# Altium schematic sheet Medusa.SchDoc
size A3; SheetNumber: 1; SheetTotal: 3
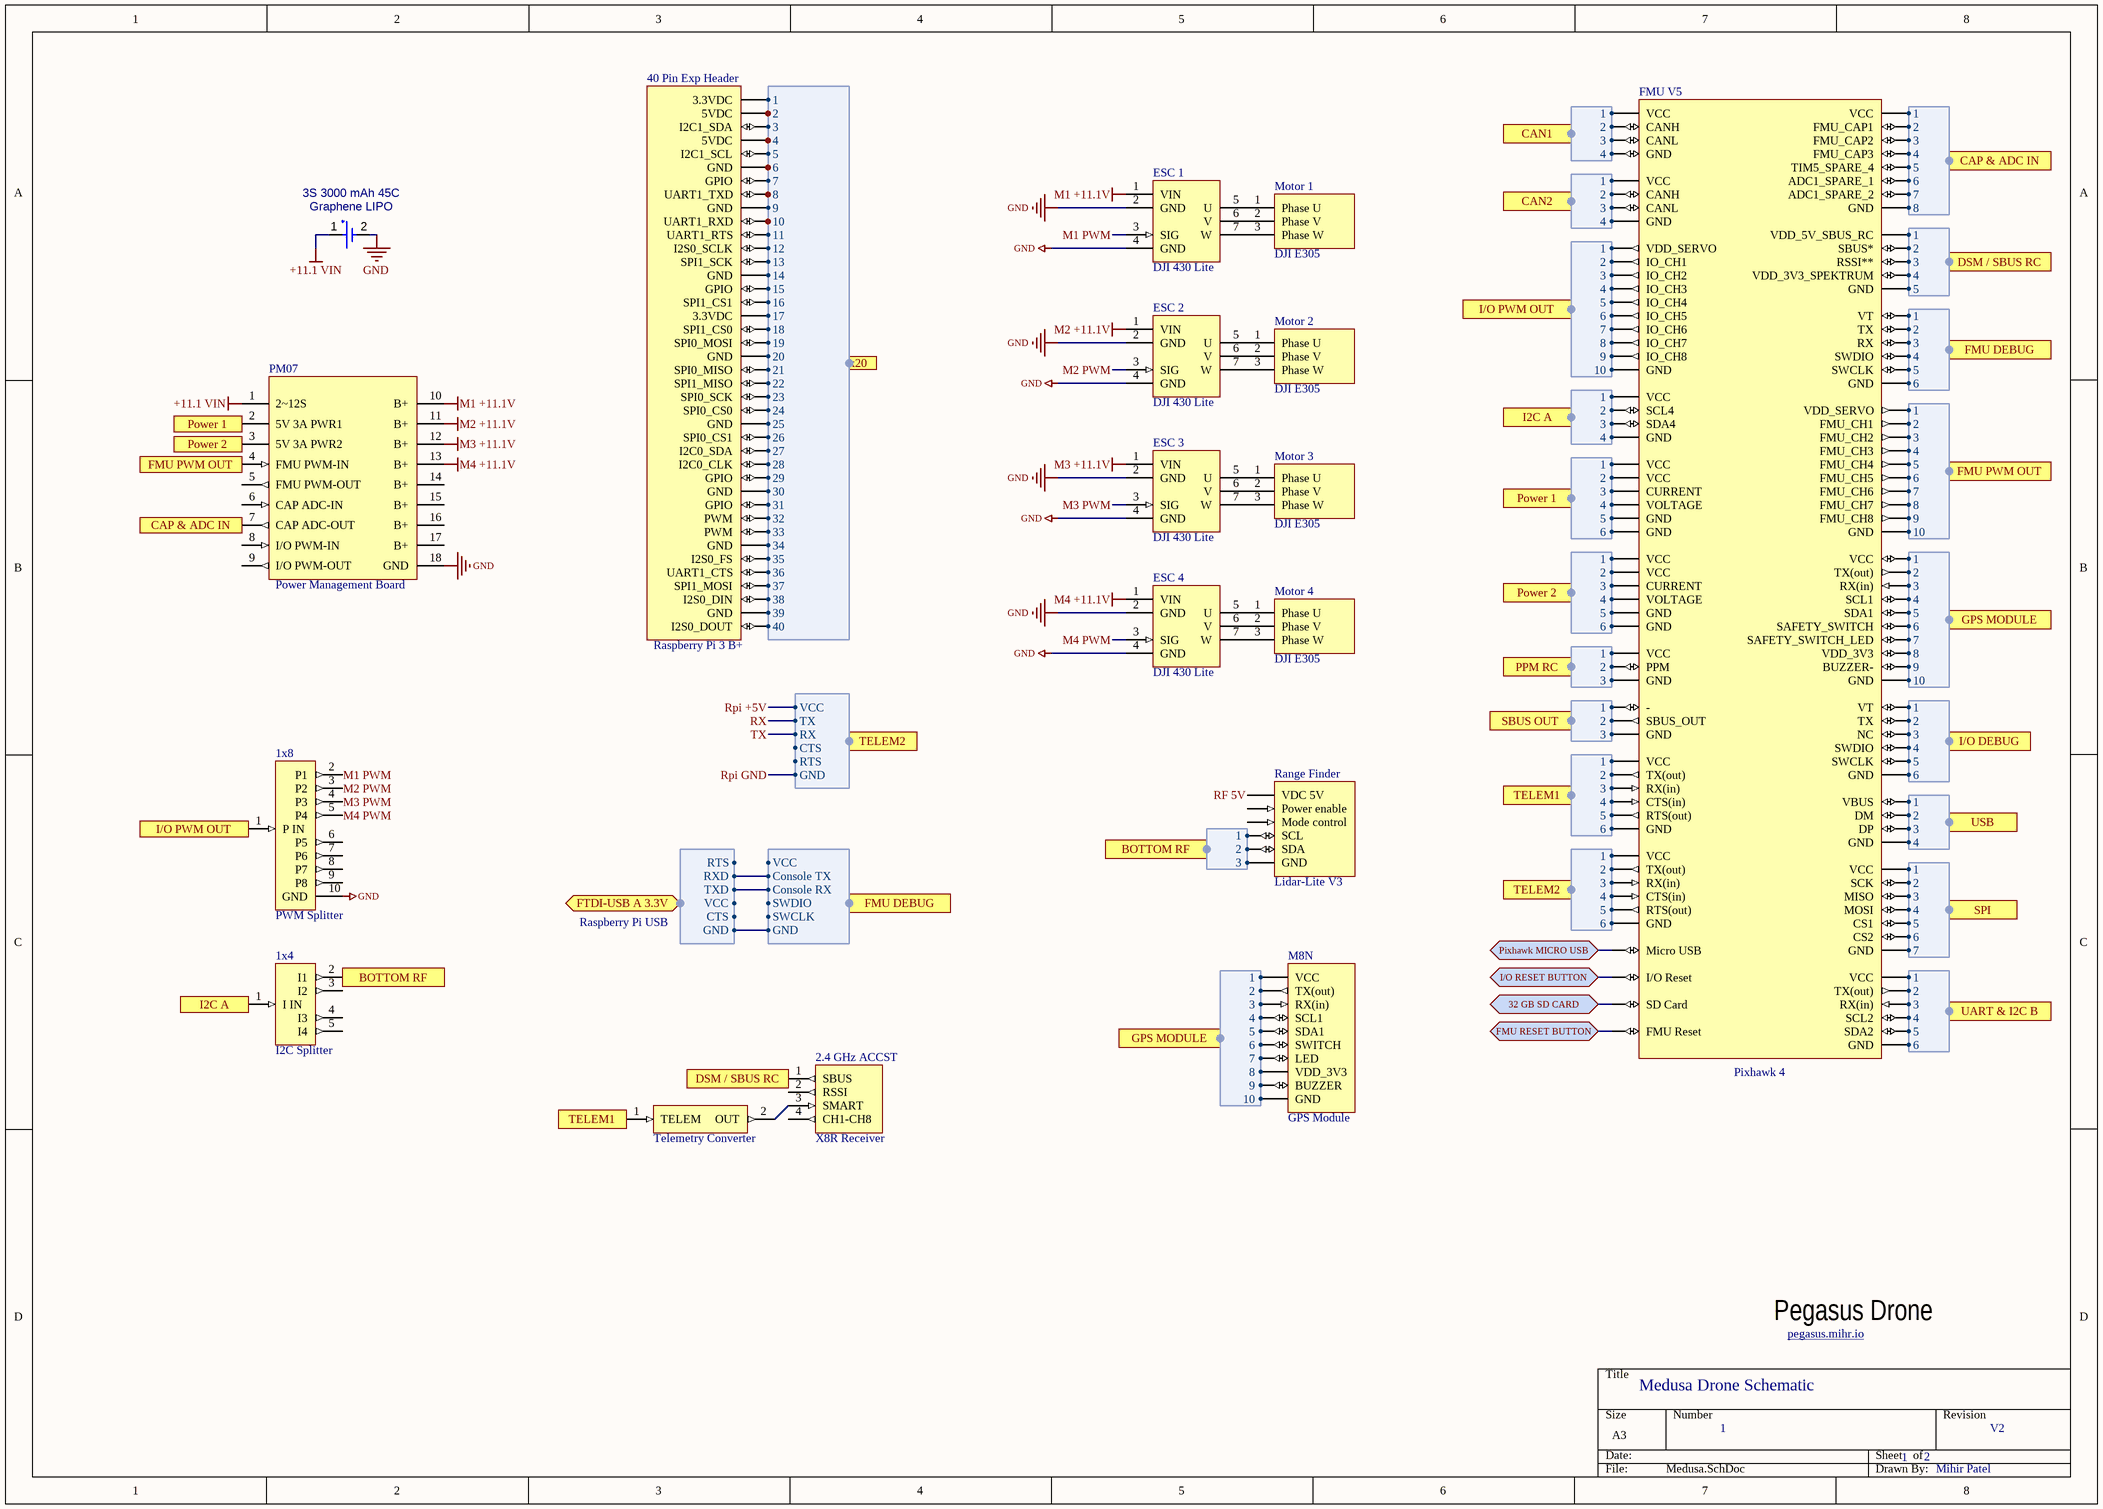
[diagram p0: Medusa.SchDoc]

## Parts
1x4  I2C Splitter
1x8  PWM Splitter
2.4_GHz_ACCST  X8R Receiver
3S_3000_mAh_45C  Graphene LIPO  [SEIK-MS621FE-FL11E-2_V]
40_Pin_Exp_Header  Raspberry Pi 3 B+
ESC_1  DJI 430 Lite
ESC_2  DJI 430 Lite
ESC_3  DJI 430 Lite
ESC_4  DJI 430 Lite
FMU_V5  Pixhawk 4
M8N  GPS Module
Motor_1  DJI E305
Motor_2  DJI E305
Motor_3  DJI E305
Motor_4  DJI E305
PM07  Power Management Board
Range_Finder  Lidar-Lite V3
TC?  Telemetry Converter

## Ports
2x20 (harness NX), 32 GB SD CARD (bidir), BOTTOM RF (harness *), BOTTOM RF (harness xx), CAN1 (harness CAN1), CAN2 (harness CAN2), CAP & ADC IN (harness CAP & ADC IN), DSM / SBUS RC (harness DSM / SBUS RC), FMU DEBUG (harness FDD), FMU DEBUG (harness FMU DEBUG), FMU PWM OUT (harness FMU PWM OUT), FMU RESET BUTTON (bidir), FTDI-USB A 3.3V (bidir, harness USBD), GPS MODULE (harness GPS MODULE), GPS MODULE (harness GPS), I2C A (harness I2C A), I/O DEBUG (harness IO DEBUG), I/O PWM OUT (harness I/O PWM OUT), I/O RESET BUTTON (bidir), Pixhawk MICRO USB (bidir), Power 1 (harness Power 1), Power 2 (harness Power 2), PPM RC (harness PPM RC), SBUS OUT (harness SBUS OUT), SPI (harness SPI), TELEM1 (harness TELEM1), TELEM2 (harness TELEM2), TELEM2 (harness X1), UART & I2C B (harness UART & I2C B), USB (harness USB)

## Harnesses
CAP & ADC IN: 1, 2, 3, 4, 5, 6, 7, 8
DSM / SBUS RC: 1, 2, 3, 4, 5
FMU DEBUG: 1, 2, 3, 4, 5, 6
FMU PWM OUT: 1, 2, 3, 4, 5, 6, 7, 8, 9, 10
IO DEBUG: 1, 2, 3, 4, 5, 6
SPI: 1, 2, 3, 4, 5, 6, 7
CAN1: 1, 2, 3, 4
CAN2: 1, 2, 3, 4
I/O PWM OUT: 1, 2, 3, 4, 5, 6, 7, 8, 9, 10
I2C A: 1, 2, 3, 4
Power 1: 1, 2, 3, 4, 5, 6
Power 2: 1, 2, 3, 4, 5, 6
SBUS OUT: 1, 2, 3
TELEM1: 1, 2, 3, 4, 5, 6
TELEM2: 1, 2, 3, 4, 5, 6
GPS MODULE: 1, 2, 3, 4, 5, 6, 7, 8, 9, 10
PPM RC: 1, 2, 3
USB: 1, 2, 3, 4
UART & I2C B: 1, 2, 3, 4, 5, 6
GPS: 1, 2, 3, 4, 5, 6, 7, 8, 9, 10
NX: 1, 2, 3, 4, 5, 6, 7, 8, 9, 10, 11, 12, 13, 14, 15, 16, 17, 18, 19, 20, 21, 22, 23, 24, 25, 26, 27, 28, 29, 30, 31, 32, 33, 34, 35, 36, 37, 38, 39, 40
FDD: VCC, Console TX, Console RX, SWDIO, SWCLK, GND
USBD: GND, CTS, VCC, TXD, RXD, RTS
xx: 1, 2, 3
X1: VCC, TX, RX, CTS, RTS, GND

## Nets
+11.1 VIN: 3S_3000_mAh_45C.1(+) PM07.1(2~12S)
GND: 1x8.10(GND) 3S_3000_mAh_45C.2(-) ESC_1.2(GND) ESC_1.4(GND) ESC_2.2(GND) ESC_2.4(GND) ESC_3.2(GND) ESC_3.4(GND) ESC_4.2(GND) ESC_4.4(GND) PM07.18(GND)
M1 +11.1V: ESC_1.1(VIN) PM07.10(B+)
M2 +11.1V: ESC_2.1(VIN) PM07.11(B+)
M3 +11.1V: ESC_3.1(VIN) PM07.12(B+)
M4 +11.1V: ESC_4.1(VIN) PM07.13(B+)
32 GB SD CARD: FMU_V5.117(SD_Card) ; port 32 GB SD CARD
FMU RESET BUTTON: FMU_V5.118(FMU_Reset) ; port FMU RESET BUTTON
I/O RESET BUTTON: FMU_V5.116(I/O_Reset) ; port I/O RESET BUTTON
M1 PWM: 1x8.2(P1) ESC_1.3(SIG)
M2 PWM: 1x8.3(P2) ESC_2.3(SIG)
M3 PWM: 1x8.4(P3) ESC_3.3(SIG)
M4 PWM: 1x8.5(P4) ESC_4.3(SIG)
Pixhawk MICRO USB: FMU_V5.115(Micro_USB) ; port Pixhawk MICRO USB
RF 5V: 40_Pin_Exp_Header.2(5VDC) Range_Finder.1(VDC_5V) ; harness NX.2
Rpi +5V: 40_Pin_Exp_Header.4(5VDC) ; harness NX.4, port TELEM2.VCC
Rpi GND: 40_Pin_Exp_Header.6(GND) ; harness NX.6, port TELEM2.GND
RX: 40_Pin_Exp_Header.10(UART1_RXD) ; harness NX.10, port TELEM2.TX
TX: 40_Pin_Exp_Header.8(UART1_TXD) ; harness NX.8, port TELEM2.RX
Net2.4_GHz_ACCST_3: 2.4_GHz_ACCST.3(SMART) TC?.2(OUT)
Net40_Pin_Exp_Header_1: 40_Pin_Exp_Header.1(3.3VDC) ; harness NX.1
Net40_Pin_Exp_Header_3: 40_Pin_Exp_Header.3(I2C1_SDA) ; harness NX.3
Net40_Pin_Exp_Header_5: 40_Pin_Exp_Header.5(I2C1_SCL) ; harness NX.5
Net40_Pin_Exp_Header_7: 40_Pin_Exp_Header.7(GPIO) ; harness NX.7
Net40_Pin_Exp_Header_9: 40_Pin_Exp_Header.9(GND) ; harness NX.9
Net40_Pin_Exp_Header_11: 40_Pin_Exp_Header.11(UART1_RTS) ; harness NX.11
Net40_Pin_Exp_Header_12: 40_Pin_Exp_Header.12(I2S0_SCLK) ; harness NX.12
Net40_Pin_Exp_Header_13: 40_Pin_Exp_Header.13(SPI1_SCK) ; harness NX.13
Net40_Pin_Exp_Header_14: 40_Pin_Exp_Header.14(GND) ; harness NX.14
Net40_Pin_Exp_Header_15: 40_Pin_Exp_Header.15(GPIO) ; harness NX.15
Net40_Pin_Exp_Header_16: 40_Pin_Exp_Header.16(SPI1_CS1) ; harness NX.16
Net40_Pin_Exp_Header_17: 40_Pin_Exp_Header.17(3.3VDC) ; harness NX.17
Net40_Pin_Exp_Header_18: 40_Pin_Exp_Header.18(SPI1_CS0) ; harness NX.18
Net40_Pin_Exp_Header_19: 40_Pin_Exp_Header.19(SPI0_MOSI) ; harness NX.19
Net40_Pin_Exp_Header_20: 40_Pin_Exp_Header.20(GND) ; harness NX.20
Net40_Pin_Exp_Header_21: 40_Pin_Exp_Header.21(SPI0_MISO) ; harness NX.21
Net40_Pin_Exp_Header_22: 40_Pin_Exp_Header.22(SPI1_MISO) ; harness NX.22
Net40_Pin_Exp_Header_23: 40_Pin_Exp_Header.23(SPI0_SCK) ; harness NX.23
Net40_Pin_Exp_Header_24: 40_Pin_Exp_Header.24(SPI0_CS0) ; harness NX.24
Net40_Pin_Exp_Header_25: 40_Pin_Exp_Header.25(GND) ; harness NX.25
Net40_Pin_Exp_Header_26: 40_Pin_Exp_Header.26(SPI0_CS1) ; harness NX.26
Net40_Pin_Exp_Header_27: 40_Pin_Exp_Header.27(I2C0_SDA) ; harness NX.27
Net40_Pin_Exp_Header_28: 40_Pin_Exp_Header.28(I2C0_CLK) ; harness NX.28
Net40_Pin_Exp_Header_29: 40_Pin_Exp_Header.29(GPIO) ; harness NX.29
Net40_Pin_Exp_Header_30: 40_Pin_Exp_Header.30(GND) ; harness NX.30
Net40_Pin_Exp_Header_31: 40_Pin_Exp_Header.31(GPIO) ; harness NX.31
Net40_Pin_Exp_Header_32: 40_Pin_Exp_Header.32(PWM) ; harness NX.32
Net40_Pin_Exp_Header_33: 40_Pin_Exp_Header.33(PWM) ; harness NX.33
Net40_Pin_Exp_Header_34: 40_Pin_Exp_Header.34(GND) ; harness NX.34
Net40_Pin_Exp_Header_35: 40_Pin_Exp_Header.35(I2S0_FS) ; harness NX.35
Net40_Pin_Exp_Header_36: 40_Pin_Exp_Header.36(UART1_CTS) ; harness NX.36
Net40_Pin_Exp_Header_37: 40_Pin_Exp_Header.37(SPI1_MOSI) ; harness NX.37
Net40_Pin_Exp_Header_38: 40_Pin_Exp_Header.38(I2S0_DIN) ; harness NX.38
Net40_Pin_Exp_Header_39: 40_Pin_Exp_Header.39(GND) ; harness NX.39
Net40_Pin_Exp_Header_40: 40_Pin_Exp_Header.40(I2S0_DOUT) ; harness NX.40
NetESC_1_5: ESC_1.5(U) Motor_1.1(Phase_U)
NetESC_1_6: ESC_1.6(V) Motor_1.2(Phase_V)
NetESC_1_7: ESC_1.7(W) Motor_1.3(Phase_W)
NetESC_2_5: ESC_2.5(U) Motor_2.1(Phase_U)
NetESC_2_6: ESC_2.6(V) Motor_2.2(Phase_V)
NetESC_2_7: ESC_2.7(W) Motor_2.3(Phase_W)
NetESC_3_5: ESC_3.5(U) Motor_3.1(Phase_U)
NetESC_3_6: ESC_3.6(V) Motor_3.2(Phase_V)
NetESC_3_7: ESC_3.7(W) Motor_3.3(Phase_W)
NetESC_4_5: ESC_4.5(U) Motor_4.1(Phase_U)
NetESC_4_6: ESC_4.6(V) Motor_4.2(Phase_V)
NetESC_4_7: ESC_4.7(W) Motor_4.3(Phase_W)
NetFMU_V5_1: FMU_V5.1(VCC) ; port Power 1.1
NetFMU_V5_2: FMU_V5.2(VCC) ; port Power 1.2
NetFMU_V5_3: FMU_V5.3(CURRENT) ; port Power 1.3
NetFMU_V5_4: FMU_V5.4(VOLTAGE) ; port Power 1.4
NetFMU_V5_5: FMU_V5.5(GND) ; port Power 1.5
NetFMU_V5_6: FMU_V5.6(GND) ; port Power 1.6
NetFMU_V5_7: FMU_V5.7(VCC) ; port Power 2.1
NetFMU_V5_8: FMU_V5.8(VCC) ; port Power 2.2
NetFMU_V5_9: FMU_V5.9(CURRENT) ; port Power 2.3
NetFMU_V5_10: FMU_V5.10(VOLTAGE) ; port Power 2.4
NetFMU_V5_11: FMU_V5.11(GND) ; port Power 2.5
NetFMU_V5_12: FMU_V5.12(GND) ; port Power 2.6
NetFMU_V5_13: FMU_V5.13(VCC) ; port TELEM1.1
NetFMU_V5_14: FMU_V5.14(TX(out)) ; port TELEM1.2
NetFMU_V5_15: FMU_V5.15(RX(in)) ; port TELEM1.3
NetFMU_V5_16: FMU_V5.16(CTS(in)) ; port TELEM1.4
NetFMU_V5_17: FMU_V5.17(RTS(out)) ; port TELEM1.5
NetFMU_V5_18: FMU_V5.18(GND) ; port TELEM1.6
NetFMU_V5_19: FMU_V5.19(VBUS) ; port USB.1
NetFMU_V5_20: FMU_V5.20(DM) ; port USB.2
NetFMU_V5_21: FMU_V5.21(DP) ; port USB.3
NetFMU_V5_22: FMU_V5.22(GND) ; port USB.4
NetFMU_V5_23: FMU_V5.23(VCC) ; port TELEM2.1
NetFMU_V5_24: FMU_V5.24(TX(out)) ; port TELEM2.2
NetFMU_V5_25: FMU_V5.25(RX(in)) ; port TELEM2.3
NetFMU_V5_26: FMU_V5.26(CTS(in)) ; port TELEM2.4
NetFMU_V5_27: FMU_V5.27(RTS(out)) ; port TELEM2.5
NetFMU_V5_28: FMU_V5.28(GND) ; port TELEM2.6
NetFMU_V5_29: FMU_V5.29(VCC) ; port CAN1.1
NetFMU_V5_30: FMU_V5.30(CANH) ; port CAN1.2
NetFMU_V5_31: FMU_V5.31(CANL) ; port CAN1.3
NetFMU_V5_32: FMU_V5.32(GND) ; port CAN1.4
NetFMU_V5_33: FMU_V5.33(VCC) ; port I2C A.1
NetFMU_V5_34: FMU_V5.34(SCL4) ; port I2C A.2
NetFMU_V5_35: FMU_V5.35(SDA4) ; port I2C A.3
NetFMU_V5_36: FMU_V5.36(GND) ; port I2C A.4
NetFMU_V5_37: FMU_V5.37(VCC) ; port CAN2.1
NetFMU_V5_38: FMU_V5.38(CANH) ; port CAN2.2
NetFMU_V5_39: FMU_V5.39(CANL) ; port CAN2.3
NetFMU_V5_40: FMU_V5.40(GND) ; port CAN2.4
NetFMU_V5_41: FMU_V5.41(-) ; port SBUS OUT.1
NetFMU_V5_42: FMU_V5.42(SBUS_OUT) ; port SBUS OUT.2
NetFMU_V5_43: FMU_V5.43(GND) ; port SBUS OUT.3
NetFMU_V5_44: FMU_V5.44(VCC) ; port PPM RC.1
NetFMU_V5_45: FMU_V5.45(PPM) ; port PPM RC.2
NetFMU_V5_46: FMU_V5.46(GND) ; port PPM RC.3
NetFMU_V5_47: FMU_V5.47(VDD_SERVO) ; port I/O PWM OUT.1
NetFMU_V5_48: FMU_V5.48(IO_CH1) ; port I/O PWM OUT.2
NetFMU_V5_49: FMU_V5.49(IO_CH2) ; port I/O PWM OUT.3
NetFMU_V5_50: FMU_V5.50(IO_CH3) ; port I/O PWM OUT.4
NetFMU_V5_51: FMU_V5.51(IO_CH4) ; port I/O PWM OUT.5
NetFMU_V5_52: FMU_V5.52(IO_CH5) ; port I/O PWM OUT.6
NetFMU_V5_53: FMU_V5.53(IO_CH6) ; port I/O PWM OUT.7
NetFMU_V5_54: FMU_V5.54(IO_CH7) ; port I/O PWM OUT.8
NetFMU_V5_55: FMU_V5.55(IO_CH8) ; port I/O PWM OUT.9
NetFMU_V5_56: FMU_V5.56(GND) ; port I/O PWM OUT.10
NetFMU_V5_57: FMU_V5.57(VCC) ; port UART & I2C B.1
NetFMU_V5_58: FMU_V5.58(TX(out)) ; port UART & I2C B.2
NetFMU_V5_59: FMU_V5.59(RX(in)) ; port UART & I2C B.3
NetFMU_V5_60: FMU_V5.60(SCL2) ; port UART & I2C B.4
NetFMU_V5_61: FMU_V5.61(SDA2) ; port UART & I2C B.5
NetFMU_V5_62: FMU_V5.62(GND) ; port UART & I2C B.6
NetFMU_V5_63: FMU_V5.63(VDD_5V_SBUS_RC) ; port DSM / SBUS RC.1
NetFMU_V5_64: FMU_V5.64(SBUS*) ; port DSM / SBUS RC.2
NetFMU_V5_65: FMU_V5.65(RSSI**) ; port DSM / SBUS RC.3
NetFMU_V5_66: FMU_V5.66(VDD_3V3_SPEKTRUM) ; port DSM / SBUS RC.4
NetFMU_V5_67: FMU_V5.67(GND) ; port DSM / SBUS RC.5
NetFMU_V5_68: FMU_V5.68(VCC) ; port CAP & ADC IN.1
NetFMU_V5_69: FMU_V5.69(FMU_CAP1) ; port CAP & ADC IN.2
NetFMU_V5_70: FMU_V5.70(FMU_CAP2) ; port CAP & ADC IN.3
NetFMU_V5_71: FMU_V5.71(FMU_CAP3) ; port CAP & ADC IN.4
NetFMU_V5_72: FMU_V5.72(TIM5_SPARE_4) ; port CAP & ADC IN.5
NetFMU_V5_73: FMU_V5.73(ADC1_SPARE_1) ; port CAP & ADC IN.6
NetFMU_V5_74: FMU_V5.74(ADC1_SPARE_2) ; port CAP & ADC IN.7
NetFMU_V5_75: FMU_V5.75(GND) ; port CAP & ADC IN.8
NetFMU_V5_76: FMU_V5.76(VCC) M8N.1(VCC) ; port GPS MODULE.1
NetFMU_V5_77: FMU_V5.77(TX(out)) M8N.2(TX(out)) ; port GPS MODULE.2
NetFMU_V5_78: FMU_V5.78(RX(in)) M8N.3(RX(in)) ; port GPS MODULE.3
NetFMU_V5_79: FMU_V5.79(SCL1) M8N.4(SCL1) ; port GPS MODULE.4
NetFMU_V5_80: FMU_V5.80(SDA1) M8N.5(SDA1) ; port GPS MODULE.5
NetFMU_V5_81: FMU_V5.81(SAFETY_SWITCH) M8N.6(SWITCH) ; port GPS MODULE.6
NetFMU_V5_82: FMU_V5.82(SAFETY_SWITCH_LED) M8N.7(LED) ; port GPS MODULE.7
NetFMU_V5_83: FMU_V5.83(VDD_3V3) M8N.8(VDD_3V3) ; port GPS MODULE.8
NetFMU_V5_84: FMU_V5.84(BUZZER-) M8N.9(BUZZER) ; port GPS MODULE.9
NetFMU_V5_85: FMU_V5.85(GND) M8N.10(GND) ; port GPS MODULE.10
NetFMU_V5_86: FMU_V5.86(VCC) ; port SPI.1
NetFMU_V5_87: FMU_V5.87(SCK) ; port SPI.2
NetFMU_V5_88: FMU_V5.88(MISO) ; port SPI.3
NetFMU_V5_89: FMU_V5.89(MOSI) ; port SPI.4
NetFMU_V5_90: FMU_V5.90(CS1) ; port SPI.5
NetFMU_V5_91: FMU_V5.91(CS2) ; port SPI.6
NetFMU_V5_92: FMU_V5.92(GND) ; port SPI.7
NetFMU_V5_93: FMU_V5.93(VDD_SERVO) ; port FMU PWM OUT.1
NetFMU_V5_94: FMU_V5.94(FMU_CH1) ; port FMU PWM OUT.2
NetFMU_V5_95: FMU_V5.95(FMU_CH2) ; port FMU PWM OUT.3
NetFMU_V5_96: FMU_V5.96(FMU_CH3) ; port FMU PWM OUT.4
NetFMU_V5_97: FMU_V5.97(FMU_CH4) ; port FMU PWM OUT.5
NetFMU_V5_98: FMU_V5.98(FMU_CH5) ; port FMU PWM OUT.6
NetFMU_V5_99: FMU_V5.99(FMU_CH6) ; port FMU PWM OUT.7
NetFMU_V5_100: FMU_V5.100(FMU_CH7) ; port FMU PWM OUT.8
NetFMU_V5_101: FMU_V5.101(FMU_CH8) ; port FMU PWM OUT.9
NetFMU_V5_102: FMU_V5.102(GND) ; port FMU PWM OUT.10
NetFMU_V5_103: FMU_V5.103(VT) ; port FMU DEBUG.1
NetFMU_V5_104: FMU_V5.104(TX) ; port FMU DEBUG.2
NetFMU_V5_105: FMU_V5.105(RX) ; port FMU DEBUG.3
NetFMU_V5_106: FMU_V5.106(SWDIO) ; port FMU DEBUG.4
NetFMU_V5_107: FMU_V5.107(SWCLK) ; port FMU DEBUG.5
NetFMU_V5_108: FMU_V5.108(GND) ; port FMU DEBUG.6
NetFMU_V5_109: FMU_V5.109(VT) ; port I/O DEBUG.1
NetFMU_V5_110: FMU_V5.110(TX) ; port I/O DEBUG.2
NetFMU_V5_111: FMU_V5.111(NC) ; port I/O DEBUG.3
NetFMU_V5_112: FMU_V5.112(SWDIO) ; port I/O DEBUG.4
NetFMU_V5_113: FMU_V5.113(SWCLK) ; port I/O DEBUG.5
NetFMU_V5_114: FMU_V5.114(GND) ; port I/O DEBUG.6
NetRange_Finder_4: Range_Finder.4(SCL) ; port BOTTOM RF.1
NetRange_Finder_5: Range_Finder.5(SDA) ; port BOTTOM RF.2
NetRange_Finder_6: Range_Finder.6(GND) ; port BOTTOM RF.3
(unnamed): port FMU DEBUG.Console TX, port FTDI-USB A 3.3V.RXD
(unnamed): port FMU DEBUG.Console RX, port FTDI-USB A 3.3V.TXD  [a separate net that carries the same name]
(unnamed): port FMU DEBUG.GND, port FTDI-USB A 3.3V.GND  [a separate net that carries the same name]

Not connected (* = marked no-connect by the designer): 1x4 1(I_IN) 2(I1) 3(I2) 4(I3) 5(I4); 1x8 1(P_IN) 6(P5) 7(P6) 8(P7) 9(P8); 2.4_GHz_ACCST 1(SBUS) 2(RSSI) 4(CH1-CH8); PM07 2(5V_3A_PWR1) 3(5V_3A_PWR2) 4(FMU_PWM-IN) 5(FMU_PWM-OUT) 6(CAP_ADC-IN) 7(CAP_ADC-OUT) 8(I/O_PWM-IN) 9(I/O_PWM-OUT) 14(B+) 15(B+) 16(B+) 17(B+); Range_Finder 2(Power_enable) 3(Mode_control); TC? 1(TELEM)

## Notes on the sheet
- Raspberry Pi USB
- Pegasus Drone
- Medusa Drone Schematic
- pegasus.mihr.io <http://pegasus.mihr.io>
- 1
- 2
- V2
- Mihir Patel

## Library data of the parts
1x4 = CMP-00028-00024-3: Holybro I2C Splitter
1x8 = CMP-00028-00022-4: Holybro PWM Splitter
2.4_GHz_ACCST = CMP-00028-00023-1: FrSky 2.4GHz ACCST
3S_3000_mAh_45C = CMP-00029-00000-1: MS Lihium Rechargeable Battery, 3 V, -20 to 60 degC, Tray
40_Pin_Exp_Header = CMP-00028-00030-3: 40 Pin Exp Header
ESC_1-ESC_4 = CMP-00028-00016-7: T-Motor ESC 600 Hz
FMU_V5 = CMP-00028-00018-8: FMU V5
M8N = CMP-00028-00021-1: Pixhawk 4 GPS Module
Motor_1-Motor_4 = CMP-00028-00017-4: KV400
PM07 = CMP-00028-00007-5: Holybro Power Module
Range_Finder = CMP-00028-00011-7: Garmin Lidar
TC? = CMP-00028-00026-1: FrSky Yappu Telemetry Converter Cable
